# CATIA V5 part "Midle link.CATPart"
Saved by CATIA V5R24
Part number: Midle link
Material "Gold": density 19320 kg/m3, Young's modulus 7.8e+10 Pa, Poisson ratio 0.42, thermal expansion 1.42e-05 1/K
Bounding box of the stored display mesh (mm): x -4.5 to 4.5, y -22.4 to -16.6, z 0 to 2.8
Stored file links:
  C:\Users\Jules\Documents\ECL\Watch\Midle link.CATPart
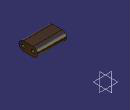
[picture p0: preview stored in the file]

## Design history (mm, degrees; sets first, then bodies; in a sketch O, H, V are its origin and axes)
Body1 (main body)
  Sketch1 on yz-plane, origin (0, 0, 0), H (0, 1, 0), V (0, 0, 1)
    line L1 (-21, 2.8) -> (-18, 2.8)
    arc A1 centre (-18, 1.4) radius 1.4 from (-18, 2.8) to (-18, 0) cw
    point P3 (-18, 1.4)
    point P4 (-18, 0)
    line L2 (-18, 0) -> (-21, 0)
    arc A2 centre (-21, 1.4) radius 1.4 from (-21, 0) to (-21, 2.8) cw
    circle A3 centre (-18, 1.4) radius 0.55
    circle A4 centre (-21, 1.4) radius 0.55
    radius A1 = 1.4
    length L2 = 3
    distance P3 V = 18
    radius A3 = 0.55
    radius A4 = 0.55
    horizontal: L1 H
    coincidence: P4 H
    tangency: A1 L1, L2 A1, A2 L1, A2 L2
  Pad1: profile Sketch1, direction (1, 0, 0), length 4.5, mirrored extent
